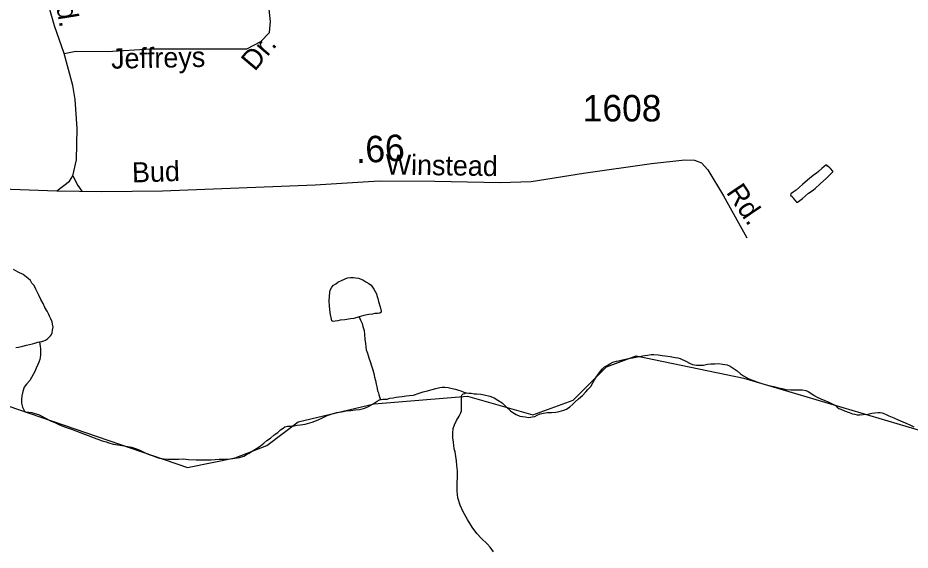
# Model space of a CAD drawing. Extents: x 2126262 to 2293712, y 749403 to 919119.
# Drawn here: x 2224251 to 2228468, y 809330 to 811845 of the extents above; entities that cross this region are included whole.
import ezdxf

# ---------------------------------------------------------------- set-up
doc = ezdxf.new("R2010")
doc.units = 0
for name, color, linetype in [('Exist Hydrographic Misc Water Feature', 7, 'Continuous'), ('Exist Road Non-System Type 51', 7, 'Continuous'), ('Exist Road Non-System Type 51 Label', 7, 'Continuous'), ('Exist Road Secondary Mileage Hundredths English Label', 7, 'Continuous'), ('Exist Road Secondary Type 51 Attributed', 7, 'Continuous'), ('Exist Road Secondary Type 51 Label', 7, 'Continuous'), ('Exist Road Secondary Type 51 Number Label', 7, 'Continuous')]:
    doc.layers.add(name, color=color, linetype=linetype)

msp = doc.modelspace()

# ---------------------------------------------------------------- linework, layer by layer
at = {"layer": 'Exist Hydrographic Misc Water Feature'}
for points in [[(2227982.5, 811077.9), (2227958.8, 811057.7), (2227944.8, 811045.6), (2227929, 811031.4), (2227915.1, 811021.3), (2227905, 811013.2), (2227903, 811007.2), (2227911.4, 810999.3), (2227915.3, 810993.3), (2227923.3, 810983.5), (2227931.3, 810973.5), (2227935.4, 810973.5), (2227947.3, 810981.7), (2227959.4, 810991.7), (2227973.1, 811003.8), (2227987.1, 811016), (2228004.9, 811028), (2228018.8, 811038.2), (2228042.6, 811060.4), (2228072.4, 811086.6), (2228090.4, 811104.7), (2228102.1, 811116.8), (2228102.1, 811120.8), (2228092, 811132.8), (2228086.1, 811138.7), (2228078.1, 811144.6), (2228073.8, 811148.6), (2228069.9, 811148.6), (2228062.1, 811142.5), (2228050, 811132.4), (2228034.4, 811118.3), (2228024.4, 811110.2), (2228016.4, 811104.1), (2228002.2, 811094), (2227982.5, 811077.9)], [(2224354.1, 810314.6), (2224364, 810316.7), (2224374, 810318.8), (2224382, 810322.9), (2224392.1, 810328.9), (2224399.9, 810337), (2224405.8, 810343), (2224409.7, 810349.1), (2224413.8, 810357.1), (2224415.5, 810369.1), (2224417.5, 810383.1), (2224415.3, 810397.1), (2224413.2, 810409.1), (2224407.3, 810423), (2224401.1, 810435), (2224397, 810442.9), (2224389, 810458.9), (2224378.8, 810476.8), (2224370.6, 810494.7), (2224360.5, 810514.6), (2224350.3, 810534.5), (2224336.1, 810562.4), (2224328.1, 810580.3), (2224317.9, 810592.2), (2224311.7, 810604.2), (2224299.8, 810614.1), (2224291.6, 810620), (2224275.6, 810631.8), (2224253.5, 810643.7), (2224231.3, 810655.5)], [(2225864.6, 810432.9), (2225838.5, 810424.7), (2225822.7, 810422.5), (2225796.9, 810418.4), (2225774.7, 810416.2), (2225762.9, 810414.1), (2225750.8, 810412), (2225740.7, 810409.9), (2225734.8, 810413.8), (2225726.6, 810451.8), (2225724.3, 810483.7), (2225722, 810505.7), (2225723.9, 810529.7), (2225725.7, 810547.7), (2225727.6, 810557.8), (2225735.6, 810571.8), (2225743.4, 810581.9), (2225753.2, 810587.9), (2225763.3, 810596), (2225783.4, 810606.2), (2225809, 810616.4), (2225823.1, 810618.5), (2225837.1, 810618.6), (2225847.1, 810616.7), (2225861.1, 810614.8), (2225881, 810606.9), (2225895.3, 810597), (2225909.3, 810589.2), (2225921.4, 810581.3), (2225933.5, 810563.4), (2225939.6, 810551.4), (2225945.6, 810541.5), (2225947.8, 810533.5), (2225951.7, 810519.6), (2225956, 810505.6), (2225964, 810479.7), (2225968.3, 810459.7), (2225968.3, 810453.7), (2225962.4, 810449.7), (2225950.5, 810447.5), (2225938.6, 810447.5), (2225926.5, 810445.3), (2225910.5, 810443.2), (2225886.5, 810439), (2225864.6, 810432.9)], [(2225864.6, 810432.9), (2225870.7, 810416.9), (2225878.7, 810401), (2225881, 810387.1), (2225887.1, 810367.1), (2225889.4, 810349.1), (2225891.6, 810327.1), (2225893.5, 810307.2), (2225895.7, 810291.2), (2225897.8, 810277.3), (2225904.1, 810261.3), (2225910.1, 810239.3), (2225916.2, 810221.4), (2225922.6, 810201.4), (2225928.5, 810181.5), (2225932.8, 810165.5), (2225936.7, 810147.6), (2225941, 810131.6), (2225945.1, 810113.7), (2225947.4, 810101.7), (2225949.2, 810093.7), (2225951.3, 810083.7), (2225955.6, 810073.7), (2225957.4, 810063.8), (2225961.6, 810049.8), (2225963.8, 810045.8), (2225967.7, 810041.9)], [(2224242.4, 810287.7), (2224254.3, 810289.9), (2224274.4, 810294), (2224292.2, 810298.2), (2224320.3, 810304.4), (2224332, 810308.5), (2224345.9, 810312.5), (2224354.1, 810314.6)], [(2224354.1, 810314.6), (2224354.4, 810302.7), (2224356.2, 810292.7), (2224358.2, 810282.7), (2224358.5, 810272.6), (2224358.5, 810262.6), (2224358.5, 810252.6), (2224356.8, 810240.6), (2224354.8, 810230.7), (2224350.9, 810218.7), (2224345.1, 810206.6), (2224337.1, 810190.5), (2224331.4, 810174.5), (2224323.4, 810160.4), (2224315.6, 810146.3), (2224307.6, 810132.3), (2224291.8, 810114.2), (2224281.8, 810100.1), (2224274, 810080), (2224270.3, 810060), (2224268.2, 810042.1), (2224268.6, 810024), (2224272.5, 810006.1), (2224282.8, 809986.2)], [(2224092.6, 810049.6), (2225053.6, 809721.4), (2225278.6, 809766), (2225427.7, 809825.2), (2225576.7, 809937), (2225934.6, 810021.4), (2226375.6, 810058.2), (2226684.6, 809969.9), (2226875.7, 810038.1), (2227032.6, 810195.6), (2227173.7, 810248.5), (2227682.6, 810142.8), (2228659.7, 809853.7), (2229117.6, 809863.9), (2229524.6, 809967), (2229682.7, 809976.8)], [(2226369.4, 810073.1), (2226383.3, 810071.2), (2226393.4, 810071.3), (2226407.3, 810069.4), (2226419.2, 810069.5), (2226439.3, 810067.7), (2226455.3, 810063.8), (2226481.4, 810058.1), (2226501.5, 810050.2), (2226519.5, 810038.4), (2226539.6, 810026.6), (2226555.8, 810010.7), (2226567.9, 809998.7), (2226579.8, 809988.8), (2226590, 809981), (2226606, 809971.1), (2226624.1, 809963.2), (2226648.1, 809959.4), (2226666.1, 809957.6), (2226682.1, 809959.7), (2226694, 809961.8), (2226706.1, 809967.9), (2226720, 809974), (2226736, 809978.1), (2226753.9, 809980.3), (2226773.8, 809980.4), (2226793.9, 809982.6), (2226809.9, 809984.7), (2226831.8, 809990.9), (2226843.9, 809997), (2226859.5, 810007.1), (2226873.6, 810019.2), (2226885.5, 810031.3), (2226901.3, 810045.4), (2226919.3, 810061.6), (2226935.1, 810077.7), (2226945, 810089.8), (2226958.7, 810103.9), (2226968.8, 810120), (2226976.6, 810134.1), (2226984.6, 810148.1), (2226996.2, 810164.2), (2227004.2, 810176.3), (2227014.1, 810186.3), (2227024.1, 810196.4), (2227036, 810202.5), (2227048.1, 810210.6), (2227063.7, 810218.8), (2227079.9, 810222.9), (2227089.7, 810224.9), (2227115.8, 810231.1), (2227137.7, 810235.3), (2227155.6, 810239.4), (2227187.6, 810245.7), (2227213.6, 810249.9), (2227227.5, 810252.1), (2227243.5, 810254.2), (2227257.5, 810254.2), (2227277.6, 810252.4), (2227295.6, 810250.5), (2227309.6, 810248.7), (2227333.6, 810244.9), (2227357.5, 810241.1), (2227369.6, 810239.2), (2227381.5, 810235.3), (2227411.9, 810221.6), (2227425.8, 810213.7), (2227439.8, 810207.7), (2227457.8, 810203.9), (2227475.9, 810204), (2227491.9, 810204.2), (2227509.9, 810208.4), (2227525.9, 810210.5), (2227545.8, 810210.6), (2227563.8, 810212.8), (2227581.9, 810208.9), (2227603.8, 810205.1), (2227617.8, 810199.2), (2227635.8, 810187.4), (2227650.2, 810177.5), (2227666.1, 810163.6), (2227680.1, 810153.8), (2227694.2, 810145.9), (2227706.3, 810140), (2227730.3, 810130.2), (2227748.4, 810124.3), (2227772.4, 810116.5), (2227800.5, 810108.7), (2227824.7, 810103), (2227846.6, 810097.1), (2227862.6, 810093.3), (2227882.5, 810089.4), (2227904.6, 810087.6), (2227918.6, 810087.7), (2227932.5, 810087.8), (2227946.7, 810087.9), (2227958.6, 810088), (2227974.5, 810084.2), (2227986.6, 810080.2), (2227998.7, 810072.4)], [(2225967.7, 810041.9), (2225975.7, 810043.9), (2225995.8, 810044.1), (2226009.5, 810048.2), (2226025.5, 810050.4), (2226039.5, 810052.4), (2226051.6, 810054.6), (2226067.6, 810056.7), (2226085.6, 810058.8), (2226101.6, 810060.9), (2226121.5, 810063.1), (2226147.3, 810071.3), (2226167.2, 810077.5), (2226187.3, 810083.6), (2226209.3, 810089.8), (2226227.3, 810093.9), (2226245.1, 810098.1), (2226257, 810100.2), (2226269.1, 810100.3), (2226285.1, 810098.4), (2226303, 810094.5), (2226319.4, 810090.7), (2226333.3, 810086.8), (2226345.2, 810082.9), (2226359.4, 810077.1), (2226369.4, 810073.1)], [(2224282.8, 809986.2), (2224286.9, 809984.2), (2224302.9, 809982.3), (2224316.8, 809980.5), (2224330.8, 809976.6), (2224348.8, 809970.7), (2224365, 809962.9), (2224379, 809955), (2224409.1, 809939.2), (2224425.3, 809933.3), (2224441.3, 809925.5), (2224459.3, 809917.6), (2224481.3, 809909.8), (2224505.3, 809902.1), (2224525.6, 809894.2), (2224565.6, 809878.5), (2224587.5, 809870.7), (2224607.8, 809862.8), (2224629.7, 809855), (2224649.8, 809847.2), (2224667.9, 809841.4), (2224681.8, 809837.5), (2224701.7, 809831.7), (2224724.1, 809827.8), (2224744, 809824), (2224762, 809822.1), (2224788, 809816.3), (2224802, 809812.4), (2224812, 809808.6), (2224830.1, 809800.7), (2224856.3, 809788.9), (2224874.4, 809781), (2224886.3, 809777.2), (2224902.3, 809771.3), (2224920.3, 809765.4), (2224942.2, 809761.6), (2224960.3, 809759.8), (2224970.3, 809759.9), (2224990.2, 809760.1), (2225010.3, 809760.2), (2225032.3, 809762.4), (2225058.3, 809758.5), (2225094.4, 809756.8), (2225132.3, 809757.2), (2225164.3, 809757.4), (2225202.2, 809759.8), (2225226.2, 809759.9), (2225254.3, 809762.2), (2225276.3, 809764.4), (2225298.2, 809768.5), (2225319.9, 809774.7), (2225332, 809782.8), (2225344.1, 809788.9), (2225363.8, 809801), (2225379.8, 809811.2), (2225397.9, 809823.3), (2225413.4, 809835.4), (2225427.6, 809847.6), (2225445.2, 809859.7), (2225463.3, 809875.8), (2225479.1, 809885.9), (2225493, 809898.1), (2225505.1, 809906.2), (2225513.1, 809912.2), (2225524.8, 809916.3), (2225548.8, 809916.5), (2225570.7, 809920.7), (2225586.7, 809922.8), (2225608.9, 809925), (2225642.9, 809935.2), (2225670.6, 809945.5), (2225690.5, 809955.7), (2225712.6, 809965.8), (2225736.2, 809974), (2225758.3, 809980.2), (2225780.3, 809984.3), (2225802.2, 809988.5), (2225824.4, 809990.7), (2225846.1, 809992.9), (2225866, 809995), (2225884, 809999.1), (2225894.1, 810003.3), (2225908, 810009.4), (2225920.1, 810015.5), (2225929.8, 810021.6), (2225949.9, 810033.8), (2225959.7, 810039.8), (2225967.7, 810041.9)], [(2226499.2, 809322.5), (2226483.2, 809344.3), (2226469.1, 809360.2), (2226442.8, 809386), (2226420.9, 809409.8), (2226398.5, 809439.6), (2226376, 809475.4), (2226355.9, 809511.2), (2226341.5, 809543.1), (2226331.3, 809577), (2226327, 809608.9), (2226326.7, 809646.9), (2226328.6, 809676.9), (2226328.4, 809704.9), (2226326.1, 809730.9), (2226324.1, 809752.9), (2226321.8, 809772.9), (2226317.5, 809794.8), (2226313.6, 809808.8), (2226311.4, 809824.8), (2226309.3, 809840.7), (2226307.1, 809860.7), (2226306.9, 809882.7), (2226308.7, 809904.7), (2226314.7, 809922.7), (2226324.3, 809942.8), (2226336.4, 809962.9), (2226344, 809978.9), (2226348.1, 809989), (2226347.9, 810001), (2226347.9, 810015), (2226347.9, 810029), (2226347.5, 810044.9), (2226347.5, 810056.9), (2226349.3, 810063), (2226355.3, 810069), (2226363.2, 810071.1), (2226369.4, 810073.1)], [(2227998.7, 810072.4), (2228014.7, 810060.5), (2228028.9, 810052.6), (2228046.7, 810044.8), (2228065, 810036.9), (2228081, 810031.1), (2228099, 810021.2), (2228113, 810015.3), (2228123.2, 810005.5), (2228131.4, 809999.5), (2228141.3, 809995.6), (2228157.2, 809987.7), (2228179.4, 809979.9), (2228195.4, 809974), (2228207.5, 809972.1), (2228217.5, 809970.2), (2228229.6, 809970.3), (2228245.6, 809970.4), (2228267.4, 809972.6), (2228287.3, 809976.7), (2228301.4, 809978.9), (2228317.4, 809981), (2228327.2, 809981.1), (2228335.2, 809979.1), (2228351.2, 809973.3), (2228367.2, 809965.4), (2228391.6, 809955.6), (2228411.5, 809945.7), (2228433.7, 809935.9), (2228451.9, 809928.1), (2228465.9, 809922.3), (2228485.7, 809912.4)]]:
    msp.add_lwpolyline(points, dxfattribs=at)
at = {"layer": 'Exist Road Non-System Type 51'}
for points in [[(2224470.2, 811675.9), (2224524.8, 811687.8), (2224674.1, 811686.4), (2224879.3, 811698.9), (2225128.3, 811698.9), (2225266.5, 811697.5), (2225333.5, 811698.9), (2225399.1, 811732.5), (2225440.2, 811775.1), (2225445.8, 811828.1), (2225436, 811913.3), (2225413.7, 811982.5), (2225394.2, 812024.4), (2225371.9, 812057.9), (2225338.4, 812069.1), (2225285.3, 812077.5), (2225265.8, 812091.4), (2225221.1, 812085.8), (2225189, 812055.1), (2225166.7, 812010.4)], [(2224511.4, 811098.4), (2224535.3, 811052.3), (2224554, 811025.9)]]:
    msp.add_lwpolyline(points, dxfattribs=at)
at = {"layer": 'Exist Road Secondary Type 51 Attributed'}
for points in [[(2224435.3, 811027.8), (2224496, 811073.2), (2224511.4, 811098.4), (2224528.1, 811173.8), (2224532.3, 811321.8), (2224521.9, 811459.4), (2224510.7, 811525), (2224470.2, 811675.9), (2224424.9, 811806.5), (2224392.8, 811916.8)], [(2218475.7, 810393.1), (2219107.5, 810586.5), (2219402.6, 810669.6), (2219593.8, 810717.1), (2219780.1, 810754.1), (2219948.9, 810770.8), (2220676.7, 810820.4), (2221289.3, 810915.4), (2222279.4, 811125.6), (2222388.2, 811134), (2222467.7, 811132.6), (2222624, 811107.4), (2222822.9, 811084.4), (2223188.5, 811066.2), (2223607.8, 811057.1), (2224435.3, 811027.8)], [(2224435.3, 811027.8), (2224648.1, 811024.3), (2224934.2, 811027.1), (2225656.4, 811055.8), (2225959.2, 811075.3), (2226222.2, 811073.2), (2226530.6, 811067.6), (2226677.1, 811071.8), (2226924.1, 811110.9), (2227245.8, 811156.3), (2227403.5, 811174.5), (2227449.5, 811173.1), (2227481.6, 811160.5), (2227512.3, 811127), (2227586.3, 811004.1), (2227696.3, 810804.8)]]:
    msp.add_lwpolyline(points, dxfattribs=at)

# ---------------------------------------------------------------- texts
at = {"layer": 'Exist Road Non-System Type 51 Label'}
for s, rotation, p in [('Dr.', 49.7917, (2225370.7, 811588.6)), ('Jeffreys', 1.1526, (2224692.9, 811604.2))]:
    msp.add_text(s, height=95, rotation=rotation, dxfattribs=at).set_placement(p)
at = {"layer": 'Exist Road Secondary Mileage Hundredths English Label'}
msp.add_text('.66', height=125, rotation=3.2155, dxfattribs=at).set_placement((2225850.3, 811157.3))
at = {"layer": 'Exist Road Secondary Type 51 Label'}
for s, rotation, p in [('Rd.', 279.0987, (2224418.8, 811990.1)), ('Winstead', 359.1962, (2225989.1, 811104.6)), ('Bud', 1.8809, (2224792.1, 811066.7)), ('Rd.', 304.0148, (2227596.2, 811020.5))]:
    msp.add_text(s, height=95, rotation=rotation, dxfattribs=at).set_placement(p)
at = {"layer": 'Exist Road Secondary Type 51 Number Label'}
msp.add_text('1608', height=125, dxfattribs=at).set_placement((2226920.8, 811355.4))

doc.saveas('drawing.dxf')
